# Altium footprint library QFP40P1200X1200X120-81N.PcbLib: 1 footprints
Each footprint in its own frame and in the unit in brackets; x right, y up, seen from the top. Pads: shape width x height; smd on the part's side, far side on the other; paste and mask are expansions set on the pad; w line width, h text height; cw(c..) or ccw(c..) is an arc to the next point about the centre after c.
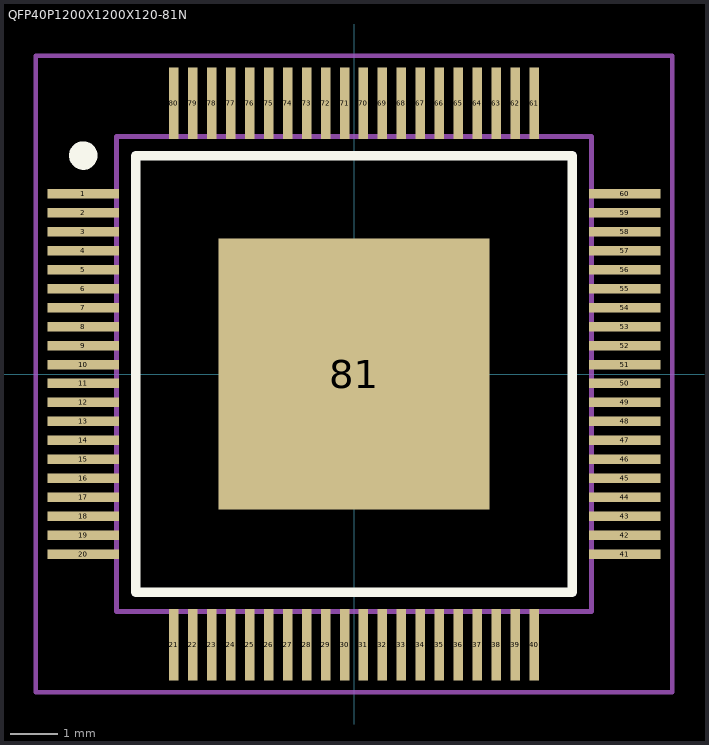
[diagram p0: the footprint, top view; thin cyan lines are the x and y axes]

## QFP40P1200X1200X120-81N [mm] "QFP,0.40mm pitch,square;80 pin,10.00mm L X 10.00mm W X 1.20mm H body (w/thermal tab)"
height 1.2
pads (81):
  rect 1.5x0.2 smd paste+0 mask+0: 1(-5.7,3.8) 2(-5.7,3.4) 3(-5.7,3) 4(-5.7,2.6) 5(-5.7,2.2) 6(-5.7,1.8) 7(-5.7,1.4) 8(-5.7,1) 9(-5.7,0.6) 10(-5.7,0.2) 11(-5.7,-0.2) 12(-5.7,-0.6) 13(-5.7,-1) 14(-5.7,-1.4) 15(-5.7,-1.8) 16(-5.7,-2.2) 17(-5.7,-2.6) 18(-5.7,-3) 19(-5.7,-3.4) 20(-5.7,-3.8) 41(5.7,-3.8) 42(5.7,-3.4) 43(5.7,-3) 44(5.7,-2.6) 45(5.7,-2.2) 46(5.7,-1.8) 47(5.7,-1.4) 48(5.7,-1) 49(5.7,-0.6) 50(5.7,-0.2) 51(5.7,0.2) 52(5.7,0.6) 53(5.7,1) 54(5.7,1.4) 55(5.7,1.8) 56(5.7,2.2) 57(5.7,2.6) 58(5.7,3) 59(5.7,3.4) 60(5.7,3.8)
  rect 0.2x1.5 smd paste+0 mask+0: 21(-3.8,-5.7) 22(-3.4,-5.7) 23(-3,-5.7) 24(-2.6,-5.7) 25(-2.2,-5.7) 26(-1.8,-5.7) 27(-1.4,-5.7) 28(-1,-5.7) 29(-0.6,-5.7) 30(-0.2,-5.7) 31(0.2,-5.7) 32(0.6,-5.7) 33(1,-5.7) 34(1.4,-5.7) 35(1.8,-5.7) 36(2.2,-5.7) 37(2.6,-5.7) 38(3,-5.7) 39(3.4,-5.7) 40(3.8,-5.7) 61(3.8,5.7) 62(3.4,5.7) 63(3,5.7) 64(2.6,5.7) 65(2.2,5.7) 66(1.8,5.7) 67(1.4,5.7) 68(1,5.7) 69(0.6,5.7) 70(0.2,5.7) 71(-0.2,5.7) 72(-0.6,5.7) 73(-1,5.7) 74(-1.4,5.7) 75(-1.8,5.7) 76(-2.2,5.7) 77(-2.6,5.7) 78(-3,5.7) 79(-3.4,5.7) 80(-3.8,5.7)
  rect 5.7x5.7 smd paste+0 mask+0: 81(0,0)
Top Overlay:
  circle w0.3: c-5.7,4.6 r0.15
  lines w0.2: -4.6,-4.6 -4.6,4.6 4.6,4.6 4.6,-4.6 -4.6,-4.6
Mechanical 3:
  text ".DESIGNATOR" at 0,0 h1.2
Mechanical 13:
  lines w0.1: -5,-5 -5,5 5,5 5,-5 -5,-5
Mechanical 15:
  lines w0.1: -0.5,0 0.5,0 ; 0,-0.5 0,0.5 ; -6.7,-6.7 -6.7,6.7 6.7,6.7 6.7,-6.7 -6.7,-6.7
3D body: height 1.21, standoff 0, extent -6,-6 6,6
